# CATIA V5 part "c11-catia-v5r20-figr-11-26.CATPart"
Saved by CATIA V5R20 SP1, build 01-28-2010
Part number: Part1
Bounding box of the stored display mesh (mm): x -205 to 53, y -75.374 to 75.374, z 0 to 37.54
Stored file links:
  D:\v5_r20\psrt_files_downloaded\c11\c11-catia-v5r20-figr-11-26.CATPart
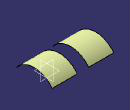
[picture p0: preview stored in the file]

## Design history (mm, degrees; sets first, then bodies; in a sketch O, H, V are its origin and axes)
Set1
  Extrude1: Element1 Sketch1, Lim1 53, Lim2 52, Direction yz-plane
  Translate1: ToTransfor Extrude1, Direction edge of Extrude1, Length 153
Body1 (main body)
  Sketch1 on yz-plane, origin (0, 0, 0), H (0, 1, 0), V (0, 0, 1)
    arc A1 centre (0, -56.4477) radius 94.1675 from (-75.3736, 0) to (75.3736, 0) cw
    point P1 (0, -56.4477)
    point P2 (-75.3736, 0)
    point P3 (75.3736, 0)
    point P4 (0, 37.7198)
    coincidence: P2 H, P3 H, A1 P4, P4 V, P1 V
